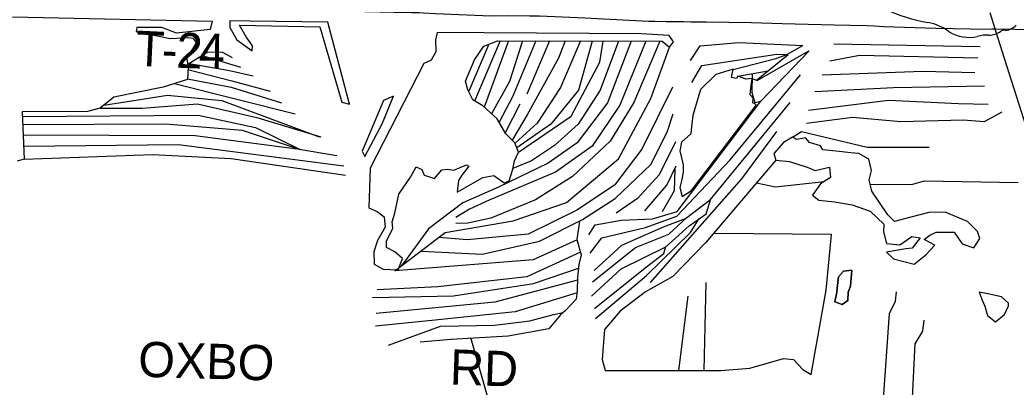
# Model space of a CAD drawing. Extents: x 0 to 34, y 0 to 22.
# Drawn here: x 6.04 to 6.844, y 14.733 to 15.029 of the extents above; entities that cross this region are included whole.
import ezdxf

# ---------------------------------------------------------------- set-up
doc = ezdxf.new("R2010")
doc.units = 0
for name, color, linetype in [('GM_X_Minor_Lake', 7, 'Continuous'), ('GM_X_Minor_River', 7, 'Continuous'), ('GM_X_State_Route', 7, 'Continuous'), ('GM_X_State_Shield', 7, 'Continuous'), ('GM_X_Township_Road', 7, 'Continuous'), ('GM_X_Township_Road_Text', 7, 'Continuous')]:
    doc.layers.add(name, color=color, linetype=linetype)

msp = doc.modelspace()

# ---------------------------------------------------------------- linework, layer by layer
at = {"layer": 'GM_X_Minor_Lake'}
for points in [[(6.20911, 15.02814), (6.20907, 15.02281), (6.2147, 15.01269), (6.227, 15.00385), (6.22741, 15.00784), (6.22214, 15.01529), (6.21688, 15.02446), (6.28173, 15.02321), (6.29954, 14.96259), (6.3058, 14.96084), (6.28823, 15.02697), (6.22559, 15.02789)], [(6.22559, 15.02789), (6.20911, 15.02814)], [(6.32235, 14.90936), (6.32135, 14.87722), (6.32799, 14.87432), (6.33366, 14.8699), (6.33436, 14.86172), (6.32838, 14.85092), (6.32527, 14.84182), (6.32558, 14.83174), (6.33297, 14.82787), (6.33867, 14.82745), (6.34495, 14.82721), (6.34844, 14.83632), (6.34239, 14.84188), (6.33557, 14.84535), (6.33541, 14.8503), (6.34063, 14.86072), (6.3401, 14.86586), (6.34224, 14.87307), (6.34559, 14.88826), (6.35482, 14.90207), (6.35945, 14.91022), (6.364, 14.90828), (6.36586, 14.90351), (6.36947, 14.90253), (6.3744, 14.90078), (6.38016, 14.90778), (6.38473, 14.9085), (6.38986, 14.9077), (6.40016, 14.912), (6.40187, 14.91085), (6.3963, 14.90347), (6.3936, 14.89931), (6.39279, 14.89247), (6.39258, 14.88981), (6.41321, 14.90163), (6.42216, 14.90327), (6.43049, 14.89751), (6.43442, 14.89892), (6.43742, 14.90848), (6.43899, 14.91513), (6.44208, 14.92214), (6.4391, 14.92977), (6.43173, 14.93706), (6.42478, 14.9489), (6.41326, 14.95945), (6.40512, 14.96427), (6.40118, 14.97247), (6.39933, 14.97933), (6.4065, 14.99659), (6.414, 15.00775), (6.42525, 15.01204), (6.55801, 15.01161), (6.56406, 15.0068), (6.56733, 15.01115), (6.56375, 15.01632), (6.54113, 15.01763), (6.4143, 15.01845)], [(6.4143, 15.01845), (6.37642, 15.01869), (6.37504, 15.0128), (6.37535, 15.0031), (6.37169, 14.99647), (6.36558, 14.99367), (6.32235, 14.90936)], [(6.5827, 14.9517), (6.58185, 14.94276), (6.58123, 14.93706), (6.57358, 14.93027), (6.57238, 14.92325), (6.57496, 14.912), (6.57492, 14.90611), (6.57392, 14.90022), (6.57235, 14.89358), (6.5742, 14.88652), (6.58176, 14.89117), (6.63407, 14.96045), (6.63123, 14.96191), (6.6314, 14.96562), (6.62902, 14.96846), (6.62959, 14.97399), (6.63068, 14.98152), (6.62588, 14.98104), (6.61924, 14.98356), (6.61809, 14.98167), (6.6139, 14.98227), (6.61544, 14.98896)], [(6.61544, 14.98896), (6.60137, 14.98484), (6.58892, 14.97257), (6.5827, 14.9517)], [(6.32747, 14.95036), (6.31579, 14.92291), (6.31804, 14.91852), (6.33213, 14.94504), (6.34123, 14.96722)], [(6.34123, 14.96722), (6.33322, 14.96386), (6.32747, 14.95036)], [(6.66319, 14.93416), (6.65593, 14.93003), (6.64807, 14.92096), (6.64974, 14.91581), (6.66095, 14.91458), (6.67518, 14.9101), (6.68144, 14.90739), (6.6862, 14.9085), (6.69306, 14.90997), (6.69395, 14.90178), (6.68573, 14.89652), (6.67939, 14.88744), (6.6845, 14.8834), (6.69723, 14.88198), (6.71148, 14.87978), (6.72589, 14.87453), (6.73704, 14.86399), (6.73661, 14.8579), (6.7392, 14.84837), (6.74985, 14.84753), (6.7596, 14.85411), (6.76625, 14.85292), (6.75991, 14.8446), (6.75477, 14.84407), (6.73915, 14.84153), (6.74482, 14.83616), (6.76153, 14.83185), (6.7709, 14.83938), (6.77819, 14.84713), (6.76947, 14.85176), (6.77406, 14.85515), (6.77922, 14.85758), (6.78644, 14.85752), (6.79386, 14.85766), (6.80026, 14.84829), (6.80955, 14.84499), (6.81455, 14.85255), (6.81251, 14.85828), (6.80458, 14.86632), (6.78637, 14.87388), (6.77344, 14.8736), (6.75876, 14.86972), (6.74561, 14.8662), (6.74033, 14.87157), (6.72735, 14.89069), (6.72513, 14.89983), (6.72709, 14.90723), (6.72487, 14.91638), (6.71673, 14.92101), (6.71045, 14.92164)], [(6.71045, 14.92164), (6.69848, 14.92286), (6.68784, 14.92408), (6.68596, 14.92733), (6.67704, 14.92987), (6.67384, 14.9337), (6.66679, 14.93242), (6.66319, 14.93416)], [(6.70039, 14.82166), (6.70442, 14.8262), (6.71108, 14.82691), (6.71004, 14.81398), (6.70829, 14.80924), (6.70786, 14.80259), (6.70346, 14.7992), (6.69739, 14.80133), (6.69897, 14.80931), (6.69937, 14.81235), (6.70039, 14.82166)], [(6.70039, 14.82166), (6.69937, 14.81235), (6.69897, 14.80931), (6.69739, 14.80133), (6.70346, 14.7992), (6.70786, 14.80259)], [(6.70786, 14.80259), (6.70829, 14.80924), (6.71004, 14.81398), (6.71108, 14.82691), (6.70442, 14.8262), (6.70039, 14.82166)], [(6.81404, 14.8092), (6.81628, 14.8029), (6.81852, 14.79794), (6.82056, 14.79032), (6.82699, 14.78532), (6.83445, 14.79116), (6.83774, 14.79817), (6.83775, 14.80046), (6.83189, 14.80545), (6.82085, 14.80777)], [(6.82085, 14.80777), (6.81404, 14.8092)]]:
    msp.add_lwpolyline(points, dxfattribs=at)
at = {"layer": 'GM_X_Minor_River'}
for points in [[(6.03377, 15.03119), (6.19484, 15.02768), (6.19308, 15.02122), (6.16605, 15.018), (6.15429, 15.02266), (6.13413, 15.02281), (6.13334, 15.01958), (6.16088, 15.01386), (6.1761, 15.01469), (6.17952, 15.0141), (6.18197, 15.01046), (6.17735, 15.0027), (6.1739, 15.00007), (6.17536, 14.99093), (6.1749, 14.98085), (6.15526, 14.97453), (6.11545, 14.96646), (6.10435, 14.95761), (6.09425, 14.95502), (6.04156, 14.95466), (6.04318, 14.91642), (6.03746, 14.91494)], [(6.34233, 14.82648), (6.38302, 14.85736), (6.43768, 14.86664), (6.48096, 14.88153), (6.52269, 14.91678), (6.54892, 14.96546), (6.56406, 15.0068)], [(6.53316, 15.01169), (6.5139, 14.96192), (6.4895, 14.92977), (6.46598, 14.91321), (6.4259, 14.89393), (6.39727, 14.88121), (6.36954, 14.86031), (6.3607, 14.84859), (6.35013, 14.83364), (6.34717, 14.83015)], [(6.5448, 15.01165), (6.52396, 14.95994), (6.50146, 14.92702), (6.47202, 14.90613), (6.4184, 14.88333), (6.40256, 14.87604), (6.39148, 14.86946)], [(6.55618, 15.01161), (6.5352, 14.96233), (6.51595, 14.93109), (6.48568, 14.90241), (6.45568, 14.88362), (6.41981, 14.86887), (6.40114, 14.86483), (6.39163, 14.86452)], [(6.41801, 15.00928), (6.4019, 14.97144)], [(6.42736, 15.01203), (6.40668, 14.96334)], [(6.43391, 15.01201), (6.4145, 14.95831)], [(6.44529, 15.01198), (6.43471, 14.97907), (6.42018, 14.95311)], [(6.45616, 15.01194), (6.43728, 14.96687), (6.42636, 14.94622)], [(6.47977, 15.01186), (6.47441, 14.99797), (6.44897, 14.95233), (6.43699, 14.93185)], [(6.52273, 15.01172), (6.50789, 14.97204), (6.49018, 14.94479), (6.47123, 14.92763), (6.45249, 14.91503), (6.43754, 14.90898)], [(6.49219, 15.01182), (6.47595, 14.97438), (6.45709, 14.94561), (6.43929, 14.92929)], [(6.50152, 15.01165), (6.49039, 14.97218), (6.46812, 14.94477), (6.44072, 14.92564)], [(6.44205, 14.92224), (6.48472, 14.95111), (6.50767, 14.99468), (6.51046, 15.01159)], [(6.46719, 15.0119), (6.44871, 14.96888)], [(6.58091, 14.99602), (6.5888, 15.00795), (6.61982, 15.01057), (6.67154, 15.00808)], [(6.61529, 14.98892), (6.64978, 14.99778), (6.65857, 15.00097), (6.67154, 15.00808)], [(6.69666, 15.0096), (6.81476, 15.00737)], [(6.17593, 14.99371), (6.19142, 15.00298), (6.20302, 15.0027), (6.21098, 14.99845)], [(6.18674, 15.00019), (6.21758, 14.9906)], [(6.58211, 14.97833), (6.5902, 14.99196), (6.65056, 15.0012), (6.65969, 15.00094)], [(6.63072, 14.98559), (6.63055, 14.97035), (6.63278, 14.96216), (6.63773, 14.96326), (6.67667, 15.00395)], [(6.63068, 14.98152), (6.63481, 14.98002), (6.67653, 15.0038)], [(6.63432, 14.9802), (6.65969, 15.00094)], [(6.69332, 14.99574), (6.71732, 15.0005), (6.81279, 14.99826)], [(6.17488, 14.9939), (6.20881, 14.98801), (6.2278, 14.98368)], [(6.17526, 14.98885), (6.21065, 14.97963), (6.24159, 14.9714)], [(6.17492, 14.98117), (6.21023, 14.97449), (6.25084, 14.96201)], [(6.49987, 14.84068), (6.50947, 14.85316), (6.54453, 14.86145), (6.5699, 14.87058), (6.61303, 14.9159), (6.66984, 14.98451)], [(6.61924, 14.98356), (6.64369, 14.98785)], [(6.68715, 14.98457), (6.76839, 14.98756), (6.81042, 14.98648)], [(6.1645, 14.9775), (6.26181, 14.95299)], [(6.5663, 14.97445), (6.54177, 14.92462), (6.51968, 14.8955), (6.4891, 14.87538), (6.44977, 14.85609), (6.40066, 14.85132), (6.3778, 14.85329)], [(6.68134, 14.97111), (6.7447, 14.97424), (6.81832, 14.97558)], [(6.10735, 14.96), (6.15883, 14.96804), (6.20255, 14.9639), (6.28126, 14.93459)], [(6.10447, 14.9577), (6.1384, 14.95754), (6.18293, 14.9612), (6.23097, 14.94999), (6.2824, 14.93439)], [(6.44313, 14.96074), (6.43129, 14.93782)], [(6.49884, 14.85552), (6.50384, 14.86348), (6.52518, 14.86731), (6.55029, 14.86826), (6.57012, 14.87438), (6.63773, 14.96326)], [(6.50319, 14.82658), (6.52541, 14.84715), (6.55918, 14.86191), (6.57692, 14.86863), (6.59701, 14.88407), (6.66131, 14.96232)], [(6.6761, 14.95612), (6.74063, 14.964), (6.7973, 14.96129), (6.82107, 14.96092)], [(6.04172, 14.95097), (6.18344, 14.95187), (6.22977, 14.94201), (6.2659, 14.9244)], [(6.36373, 14.84233), (6.41275, 14.83982), (6.45905, 14.85031), (6.4938, 14.86774), (6.52017, 14.88465), (6.54929, 14.91258), (6.56223, 14.93911), (6.5669, 14.95315)], [(6.6745, 14.94548), (6.71181, 14.95033), (6.75078, 14.94681), (6.801, 14.94814), (6.8183, 14.94686), (6.83243, 14.95455)], [(6.042, 14.94435), (6.15733, 14.94504), (6.21892, 14.94), (6.26593, 14.92439)], [(6.04235, 14.93615), (6.18103, 14.93554), (6.26331, 14.92483), (6.29542, 14.91945)], [(6.54858, 14.81692), (6.62224, 14.90061), (6.65067, 14.93882)], [(6.66319, 14.93416), (6.67064, 14.93886), (6.72343, 14.92628), (6.77364, 14.92609)], [(6.04273, 14.9271), (6.16766, 14.92841), (6.30106, 14.91123)], [(6.56882, 14.9305), (6.55569, 14.90378), (6.53805, 14.8849), (6.52103, 14.87304)], [(6.04318, 14.91642), (6.14668, 14.92039), (6.21019, 14.91706), (6.30253, 14.90361)], [(6.64977, 14.91581), (6.59313, 14.84891), (6.56668, 14.82173), (6.54453, 14.80953), (6.52425, 14.7939), (6.51159, 14.77916), (6.5097, 14.75502), (6.51191, 14.74607), (6.6053, 14.74593), (6.6289, 14.74784), (6.65597, 14.75581), (6.66414, 14.7548), (6.6715, 14.74676), (6.67832, 14.7429), (6.69042, 14.8109), (6.69475, 14.85575), (6.59967, 14.85666)], [(6.54406, 14.87477), (6.56191, 14.89556), (6.56944, 14.9111)], [(6.56818, 14.90849), (6.56777, 14.89095), (6.55813, 14.8739)], [(6.63419, 14.8974), (6.64958, 14.89413), (6.68872, 14.89843)], [(6.72606, 14.8964), (6.75934, 14.89615), (6.76982, 14.89892), (6.84551, 14.89759)], [(6.56082, 14.84557), (6.57992, 14.86271), (6.5935, 14.87249), (6.59739, 14.88453)], [(6.50179, 14.81766), (6.53642, 14.84535), (6.56351, 14.85598), (6.57802, 14.86947)], [(6.50423, 14.78797), (6.54539, 14.82265), (6.58083, 14.85737), (6.58804, 14.86856)], [(6.49136, 14.86651), (6.4893, 14.8516), (6.49263, 14.83941), (6.49086, 14.83143), (6.48965, 14.82136), (6.48956, 14.81014), (6.48856, 14.80368), (6.47974, 14.79424), (6.47611, 14.79084), (6.46651, 14.77969), (6.43375, 14.77386), (6.3877, 14.77097), (6.36277, 14.76888)], [(6.48938, 14.85133), (6.4538, 14.83533), (6.34228, 14.82647)], [(6.50113, 14.80587), (6.52488, 14.82794), (6.56089, 14.84582)], [(6.50334, 14.79596), (6.54429, 14.82874), (6.5594, 14.84042), (6.56097, 14.84611)], [(6.49208, 14.84145), (6.44875, 14.82148), (6.37699, 14.81347), (6.3279, 14.81118)], [(6.32424, 14.80493), (6.38949, 14.80634), (6.45423, 14.8163), (6.49051, 14.82853)], [(6.48963, 14.81889), (6.42311, 14.80114), (6.32718, 14.79197)], [(6.59201, 14.74595), (6.59366, 14.81696)], [(6.48935, 14.80875), (6.43941, 14.7934), (6.37203, 14.7865), (6.32654, 14.78171)], [(6.57143, 14.74598), (6.57893, 14.80604)], [(6.73634, 14.71907), (6.74145, 14.79206), (6.74647, 14.8021), (6.74728, 14.80951)], [(6.33707, 14.76641), (6.37923, 14.78188), (6.4226, 14.78269), (6.45115, 14.78609), (6.47021, 14.79108), (6.47824, 14.79283)], [(6.75992, 14.71851), (6.76238, 14.76756), (6.76854, 14.77778), (6.76956, 14.78652)], [(6.40355, 14.77197), (6.42074, 14.71138), (6.59341, 14.70684), (6.60595, 14.39845), (6.55385, 14.40056), (6.55559, 14.30241), (6.53359, 14.28451), (6.52462, 14.28307)]]:
    msp.add_lwpolyline(points, dxfattribs=at)
at = {"layer": 'GM_X_State_Route'}
for points in [[(6.8269, 15.02158), (6.82282, 15.03463)], [(6.92556, 14.70908), (6.92481, 14.71188), (6.91446, 14.74278), (6.91072, 14.75459), (6.90198, 14.78443), (6.892, 14.8155), (6.88732, 14.83029), (6.87796, 14.8599), (6.86959, 14.88656), (6.85179, 14.94282), (6.83826, 14.98577), (6.82745, 15.01981), (6.8269, 15.02158)]]:
    msp.add_lwpolyline(points, dxfattribs=at)
at = {"layer": 'GM_X_State_Shield'}
for centre, major_axis, start_param, end_param in [((6.80055, 15.12518), (0.1262, 0), 4.195997, 4.488961), ((6.76293, 14.9961), (0.03949, 0), 0.823519, 1.323587), ((6.83402, 15.0176), (0.00376, 0), 1.147584, 2.315152), ((6.83241, 15.03135), (0.01412, 0), 4.937069, 5.64225), ((6.80563, 15.03478), (0.02506, 0), 4.026481, 4.996735), ((6.82011, 15.00019), (0.02059, 0), 1.495662, 1.94098), ((6.82194, 15.02729), (0.01335, 0), 4.691044, 5.507374)]:
    msp.add_ellipse(centre, major_axis=major_axis, ratio=0.8, start_param=start_param, end_param=end_param, dxfattribs=at)
at = {"layer": 'GM_X_Township_Road'}
for points in [[(6.8269, 15.02158), (6.84267, 15.02128), (6.86908, 15.02046), (6.92034, 15.01907), (6.96382, 15.01766), (6.96689, 15.01776), (6.9684, 15.01793), (6.96989, 15.01821), (6.97137, 15.01858), (6.97424, 15.0196), (6.97699, 15.02094), (6.98097, 15.02331), (6.98614, 15.02671), (7.03406, 15.06121), (7.04691, 15.06981), (7.0658, 15.08345), (7.06713, 15.08442)], [(6.20477, 15.03853), (6.22626, 15.03796), (6.24175, 15.03756), (6.26036, 15.03719), (6.29427, 15.03625), (6.34171, 15.03515), (6.3495, 15.03502), (6.35569, 15.03486), (6.36194, 15.03471), (6.36505, 15.03443), (6.37506, 15.03391), (6.41962, 15.0322), (6.4342, 15.03227), (6.45108, 15.03224), (6.45912, 15.0321), (6.49602, 15.0306), (6.50565, 15.02996), (6.54194, 15.02819), (6.54728, 15.02782), (6.55211, 15.02774), (6.56115, 15.02766), (6.56788, 15.02748), (6.57365, 15.02758)], [(6.57365, 15.02758), (6.57529, 15.02761), (6.5811, 15.02733), (6.59075, 15.02728), (6.59366, 15.0273), (6.59956, 15.02712), (6.60428, 15.02717), (6.61192, 15.02696), (6.63011, 15.02673), (6.65485, 15.026), (6.69678, 15.02487), (6.7232, 15.02428), (6.72938, 15.02402), (6.73709, 15.02361), (6.77902, 15.02226), (6.80696, 15.02153), (6.81627, 15.02148), (6.82404, 15.02164), (6.8269, 15.02158)]]:
    msp.add_lwpolyline(points, dxfattribs=at)

# ---------------------------------------------------------------- texts
at = {"layer": 'GM_X_Township_Road_Text'}
for s, height, rotation, p in [('T', 0.02841, 357.26044, (6.13235, 14.99189)), ('2', 0.02841, 357.74224, (6.16549, 14.99033)), ('4', 0.02841, 359.0707, (6.1837, 14.98962)), ('-', 0.02841, 357.37011, (6.15364, 14.99088)), ('OXBO', 0.028409, 358.31605, (6.13485, 14.74106)), ('RD', 0.028409, 358.02441, (6.38642, 14.73481))]:
    msp.add_text(s, height=height, rotation=rotation, dxfattribs=at).set_placement(p)

doc.saveas('drawing.dxf')
